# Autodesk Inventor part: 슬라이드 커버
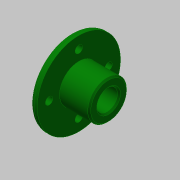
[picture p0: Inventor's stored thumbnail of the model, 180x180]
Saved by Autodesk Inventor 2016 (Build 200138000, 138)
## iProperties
Created: 2015-12
Part Number: 슬라이드 커버
Document SubType Name: Modeling
Designer: mdu
Density: 2.71 g/cm^3
Material: 알루미늄 6061
Appearance: 진녹색
Mass: 49.5251 g
Surface Area: 80.5945 cm^2
Volume: 18.2749 cm^3
Author: mdu
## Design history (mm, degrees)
sketch "스케치1"
  geometry: L1 (-12.5, 0)-(12.5, 0); L2 (-12.5, 0)-(-12.5, 28); L3 (-12.5, 28)-(-7.5, 28); L4 (-7.5, 28)-(-7.5, 13); L5 (-7.5, 13)-(12.5, 13); L6 (12.5, 13)-(12.5, 0); 2 further points
  constraints: 12 end point, 3 perpendicular, 1 coincident, 1 horizontal, 1 midpoint, 1 parallel
  dimensions: "d1" = 56 diameter of L3 L1; "d2" = 26 diameter of L5 L1; "d5" = 5 distance of L2.end L3.end; "d32" = 20 distance of L4.end L5.end
revolve "회전1" sketch "스케치1" stored, may be unused: angle "d6" = 90 deg
sketch "스케치2" dims "d33" = 40
  geometry: 3 further points
  constraints: 2 vertical alignment, 1 coincident, 2 other
hole "구멍1" sketch "스케치2" at (0, 20) diameter "d8" = 5; stored, may be unused: countersink angle "d12" = 90 deg, drill point angle "d14" = 118 deg; dims "d9" = 6, "d10" = 8, "d11" = 4.4, "d13" = 8
hole "구멍2" diameter "d20" = 14; stored, may be unused: countersink angle "d24" = 90 deg, drill point angle "d26" = 0 deg; dims "d18" = 10, "d19" = 10, "d21" = 6, "d22" = 8, "d23" = 4.4, "d25" = 8
fillet "모깎기1" dims "d27" = 3
chamfer "모따기1" distance "d29" = 1; stored, may be unused: second distance "d30" = 2, angle "d31" = 45 deg
node "솔리드1"
pattern_circular "원형 패턴1" dims angle "d16" = 360 deg
